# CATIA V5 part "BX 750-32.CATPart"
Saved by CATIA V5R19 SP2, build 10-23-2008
Part number: BX 750-32
Bounding box of the stored display mesh (mm): x -47.487 to 47.487, y -47.487 to 47.487, z 0 to 182
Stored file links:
  C:\Users\Bora\Desktop\3D Katı model\BX serisi\BX 750\BX 750-32.CATPart
  C:\Program Files\Dassault Systemes\B19\intel_a\reffiles\standard\MetricThickPitch.txt
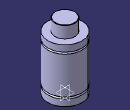
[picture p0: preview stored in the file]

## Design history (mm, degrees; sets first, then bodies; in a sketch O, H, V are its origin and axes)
Body1 (main body)
  Sketch1 on yz-plane, origin (0, 0, 0), H (0, 1, 0), V (0, 0, 1)
    point P2 (47.5, 18.5)
    line L1 (47.5, 18.5) -> (47.5, 0)
    point P3 (47.5, 23.5)
    point P4 (47.5, 126.5)
    line L2 (47.5, 126.5) -> (47.5, 23.5)
    point P6 (27.5, 181)
    arc A1 centre (26.5, 181) radius 1 from (27.5, 181) to (26.5, 182) ccw
    point P8 (27.5, 181)
    line L3 (27.5, 181) -> (27.5, 149)
    point P9 (47.5, 131.5)
    line L4 (47.5, 149) -> (47.5, 131.5)
    point P11 (47.5, 18.5)
    point P12 (47.5, 23.5)
    arc A2 centre (47.5, 21) radius 2.5 from (47.5, 23.5) to (47.5, 18.5) ccw
    point P13 (47.5, 126.5)
    point P14 (47.5, 131.5)
    arc A3 centre (47.5, 129) radius 2.5 from (47.5, 131.5) to (47.5, 126.5) ccw
    line L5 (26.5, 182) -> (0, 182)
    point P15 (0, 182)
    line L6 (27.5, 149) -> (47.5, 149)
    line L7 (47.5, 0) -> (0, 0)
    tangency: L5 A1
    coincidence: P15 V, P2 P11, P3 P12, P4 P13, P6 P8, P9 P14
    horizontal: L6 H, L7 H
  Shaft1: profile Sketch1, axis Sketch1.V, angle 360
  Sketch2 on face of Shaft1 from Sketch1.L7, origin (0, 0, 0), H (1, 0, 0), V (0, -1, 0)
    point P1 (25, 0)
    distance P1 V = 25
  Hole1: placed by Sketch2, at (25, 0, 0) direction (0, 0, 1), diameter 6.647, depth 10, threaded "M8", thread diameter 8, thread depth 10, pitch 1.25
  CircPattern1: of Hole1, instances 4, angular step 90, axis from xy-plane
